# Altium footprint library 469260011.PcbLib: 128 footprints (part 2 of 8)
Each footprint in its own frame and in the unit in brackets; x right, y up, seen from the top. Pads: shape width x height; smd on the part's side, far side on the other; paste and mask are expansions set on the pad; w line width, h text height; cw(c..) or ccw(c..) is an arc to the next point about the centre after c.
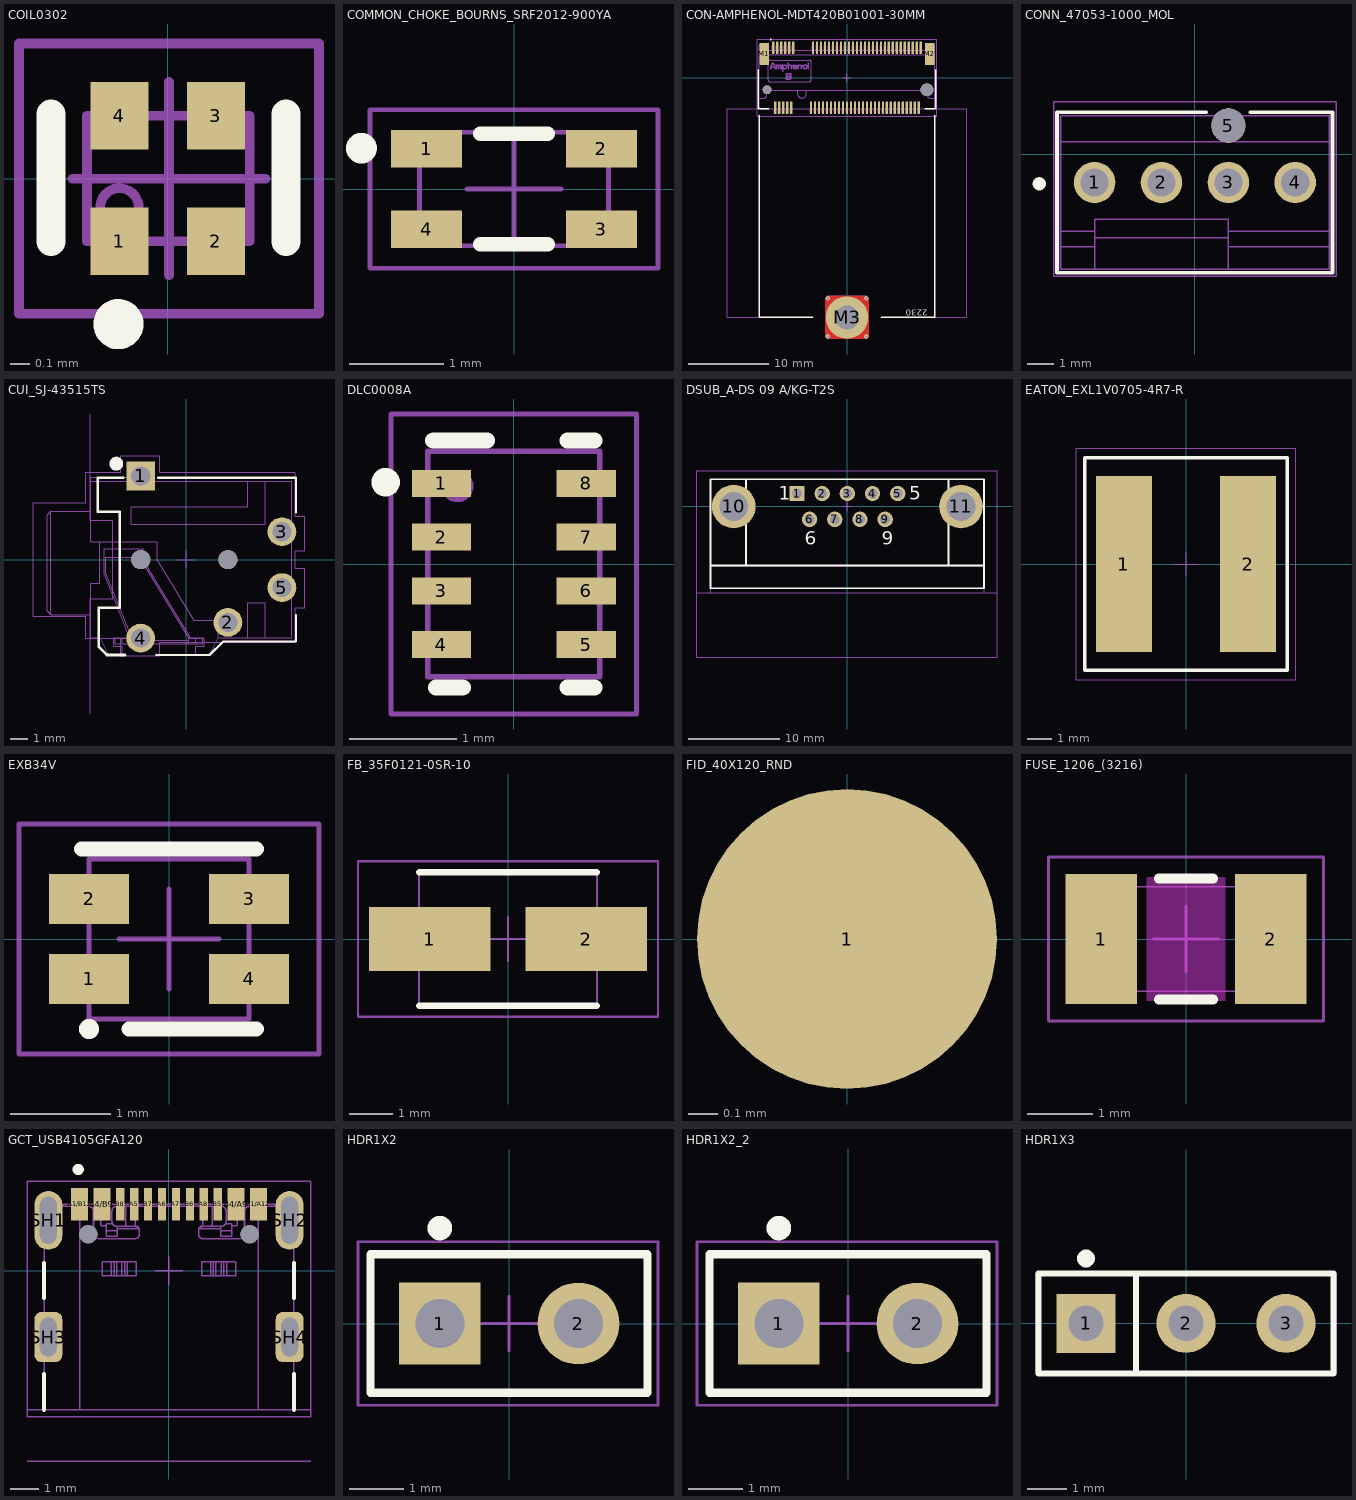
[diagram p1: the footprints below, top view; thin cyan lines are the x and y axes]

## COIL0302 [mm] "0302 (0806 Metric), 4 Lead"
height 0.5
pads (4):
  rect 0.3x0.35 smd: 1(-0.25,-0.325) 2(0.25,-0.325) 3(0.25,0.325) 4(-0.25,0.325)
Top Overlay:
  circle w0.152: c-0.255,-0.754 r0.054
  lines w0.15: -0.606,-0.325 -0.606,0.335 ; 0.614,-0.325 0.614,0.335
Top Assembly:
  circle w0.05: c-0.25,-0.15 r0.1
  lines w0.05: -0.35,-0.325 -0.35,-0.4 -0.15,-0.4 -0.15,-0.325 ; -0.35,0.325 -0.35,0.4 -0.15,0.4 -0.15,0.325 ; 0.157,-0.325 0.157,-0.4 0.357,-0.4 0.357,-0.325 ; 0.157,0.325 0.157,0.4 0.357,0.4 0.357,0.325 ; -0.418,-0.325 0.425,-0.325 0.425,0.325 -0.418,0.325 -0.418,-0.325
  text ".Designator" at -2.252,-0.226 h1
Top Courtyard:
  lines w0.05: -0.493,0 0.507,0 ; 0.007,-0.5 0.007,0.5 ; -0.77,-0.7 0.784,-0.7 0.784,0.7 -0.77,0.7 -0.77,-0.7
3D body "EXC-14CH120U.step": height 0.5, standoff 0, extent -0.425,-0.325 0.425,0.325

## COMMON_CHOKE_BOURNS_SRF2012-900YA [mm] "2.0x1.2x1.2mm"
height 2.4
pads (4):
  rect 0.75x0.4 smd: 1(-0.925,0.425) 2(0.925,0.425) 3(0.925,-0.425) 4(-0.925,-0.425)
Top Overlay:
  circle w0.254: c-1.615,0.432 r0.036
  lines w0.152: -0.356,-0.584 0.356,-0.584 ; -0.356,0.584 0.356,0.584
Top Assembly:
  lines w0.05: -1,-0.6 -1,0.6 1,0.6 1,-0.6 -1,-0.6
  text ".Designator" at -2.252,-0.226 h1
Top Courtyard:
  lines w0.05: -0.5,0 0.5,0 ; 0,-0.5 0,0.5 ; -1.524,-0.838 -1.524,0.838 1.524,0.838 1.524,-0.838 -1.524,-0.838 ; 0,0 0,0
3D body "User Library-SRF2012A.step": height 1.2, standoff 0.01, extent -1,-0.6 1,0.6

## CON-AMPHENOL-MDT420B01001-30MM [mm] "Tortadex footprint for PCIe M.2 Connectors, Storage and Server Connector, P=0.5mm, H=4.2mm, Key B, 30µin Au Plating"
height 4.2
pads (72):
  rrect10% 0.3x1.55 smd: 1(-9.25,3.775) 2(-9,-3.775) 3(-8.75,3.775) 4(-8.5,-3.775) 5(-8.25,3.775) 6(-8,-3.775) 7(-7.75,3.775) 8(-7.5,-3.775) 9(-7.25,3.775) 10(-7,-3.775) 11(-6.75,3.775) 20(-4.5,-3.775) 21(-4.25,3.775) 22(-4,-3.775) 23(-3.75,3.775) 24(-3.5,-3.775) 25(-3.25,3.775) 26(-3,-3.775) 27(-2.75,3.775) 28(-2.5,-3.775) 29(-2.25,3.775) 30(-2,-3.775) 31(-1.75,3.775) 32(-1.5,-3.775) 33(-1.25,3.775) 34(-1,-3.775) 35(-0.75,3.775) 36(-0.5,-3.775) 37(-0.25,3.775) 38(0,-3.775) 39(0.25,3.775) 40(0.5,-3.775) 41(0.75,3.775) 42(1,-3.775) 43(1.25,3.775) 44(1.5,-3.775) 45(1.75,3.775) 46(2,-3.775) 47(2.25,3.775) 48(2.5,-3.775) 49(2.75,3.775) 50(3,-3.775) 51(3.25,3.775) 52(3.5,-3.775) 53(3.75,3.775) 54(4,-3.775) 55(4.25,3.775) 56(4.5,-3.775) 57(4.75,3.775) 58(5,-3.775) 59(5.25,3.775) 60(5.5,-3.775) 61(5.75,3.775) 62(6,-3.775) 63(6.25,3.775) 64(6.5,-3.775) 65(6.75,3.775) 66(7,-3.775) 67(7.25,3.775) 68(7.5,-3.775) 69(7.75,3.775) 70(8,-3.775) 71(8.25,3.775) 72(8.5,-3.775) 73(8.75,3.775) 74(9,-3.775) 75(9.25,3.775)
  rrect10% 1.2x2.75 smd: M1(-10.35,3) M2(10.35,3)
  round 5.3 / inner round 0 / far side round 0 hole 3 unplated: M3(0,-30)
  round 1.1 hole 1.1 unplated: ""(-10,-1.5)
  round 1.6 hole 1.6 unplated: ""(10,-1.5)
via 2.4,-32.4 diameter 0.6 hole 0.3
via -2.4,-32.4 diameter 0.6 hole 0.3
via 2.4,-27.6 diameter 0.6 hole 0.3
via -2.4,-27.6 diameter 0.6 hole 0.3
Top Layer:
  region: -2.4,-27.3 -2.7,-27.6 -2.7,-32.4 -2.4,-32.7 0,-32.7 0,-31.9 -0.9,-31.9 -1.9,-30.9 -1.9,-29.1 -0.9,-28.1 0.9,-28.1 1.9,-29.1 1.9,-30.9 0.9,-31.9 0,-31.9 0,-32.7 2.4,-32.7 2.7,-32.4 2.7,-27.6 2.4,-27.3
Bottom Layer:
  region: -2.4,-27.3 -2.7,-27.6 -2.7,-32.4 -2.4,-32.7 0,-32.7 0,-31.9 -0.9,-31.9 -1.9,-30.9 -1.9,-29.1 -0.9,-28.1 0.9,-28.1 1.9,-29.1 1.9,-30.9 0.9,-31.9 0,-31.9 0,-32.7 2.4,-32.7 2.7,-32.4 2.7,-27.6 2.4,-27.3
Top Overlay:
  circle w0.15: c-9.55,4.8 r0.05
  lines w0.2: -11.1,1 -11.1,-3.9 -9.8,-3.9 ; -11,-4.7 -11,-30 -4.3,-30 ; 4.3,-30 11,-30 11,-4.7 ; 9.8,-3.9 11.1,-3.9 11.1,1
  text "2230" at 10.1,-28.815 h1.3
Top Paste:
  region: -2.542,-29.7 -2.517,-29.487 -2.397,-29.076 -2.21,-28.69 -1.962,-28.341 -1.659,-28.038 -1.31,-27.79 -0.924,-27.603 -0.513,-27.483 -0.3,-27.458 -0.3,-28.479 -0.411,-28.506 -0.627,-28.582 -0.828,-28.69 -1.012,-28.826 -1.174,-28.988 -1.31,-29.172 -1.418,-29.373 -1.494,-29.589 -1.521,-29.7
  region: 1.521,-29.7 1.494,-29.589 1.418,-29.373 1.31,-29.172 1.174,-28.988 1.012,-28.826 0.828,-28.69 0.627,-28.582 0.411,-28.506 0.3,-28.479 0.3,-27.458 0.513,-27.483 0.924,-27.603 1.31,-27.79 1.659,-28.038 1.962,-28.341 2.21,-28.69 2.397,-29.076 2.517,-29.487 2.542,-29.7
  region: 0.3,-32.542 0.3,-31.521 0.411,-31.494 0.627,-31.418 0.828,-31.31 1.012,-31.174 1.174,-31.012 1.31,-30.828 1.418,-30.627 1.494,-30.411 1.521,-30.3 2.542,-30.3 2.517,-30.513 2.397,-30.924 2.21,-31.31 1.962,-31.659 1.659,-31.962 1.31,-32.21 0.924,-32.397 0.513,-32.517
  region: -0.3,-31.521 -0.411,-31.494 -0.627,-31.418 -0.828,-31.31 -1.012,-31.174 -1.174,-31.012 -1.31,-30.828 -1.418,-30.627 -1.494,-30.411 -1.521,-30.3 -2.542,-30.3 -2.517,-30.513 -2.397,-30.924 -2.21,-31.31 -1.962,-31.659 -1.659,-31.962 -1.31,-32.21 -0.924,-32.397 -0.513,-32.517 -0.3,-32.542
Bottom Solder:
  region: -1.6,-30 -1.6,-29.842 -1.539,-29.533 -1.418,-29.242 -1.243,-28.98 -1.02,-28.757 -0.758,-28.582 -0.467,-28.462 -0.158,-28.4 0,-28.4 0.158,-28.4 0.467,-28.462 0.758,-28.582 1.02,-28.757 1.243,-28.98 1.418,-29.242 1.539,-29.533 1.6,-29.842 1.6,-30 1.6,-30.158 1.539,-30.467 1.418,-30.758 1.243,-31.02 1.02,-31.243 0.758,-31.418 0.467,-31.539 0.158,-31.6 0,-31.6 -0.158,-31.6 -0.467,-31.539 -0.758,-31.418 -1.02,-31.243 -1.243,-31.02 -1.418,-30.758 -1.539,-30.467 -1.6,-30.158
Top Assembly:
  drawing of 2595 lines, arcs and shapes, not listed
  text ".Designator" at -2.252,-0.226 h1
Top Courtyard:
  lines w0.05: -0.5,0 0.5,0 ; 0,-0.5 0,0.5 ; -11.25,-4.8 -11.25,4.8 11.25,4.8 11.25,-4.8 -11.25,-4.8
3D body "User Library-m2_type3052_b_4ant-1.STEP": height 4.69, standoff 1.19, extent -15,-52 15,0
3D body "c-2199230-1-b3-3d.stp": height 4.1, standoff -0.6, extent -10.939,-4.378 10.961,4.322

## CONN_47053-1000_MOL [mil]
height 295.28
pads (5):
  round 62 / inner round 60 / far side round 62 hole 42 paste+0 mask+0: 1(-150,-42.52) 2(-50,-42.52) 3(50,-42.52) 4(150,-42.52)
  round 51 / inner round 60 / far side round 51 hole 51 unplated paste+0 mask-25.5: 5(50,42.52)
Top Overlay:
  circle w9.84: c-232.68,-44.49 r4.92
  lines w5.91: 16.96,62.48 -206,62.48 -206,-177.52 206,-177.52 206,62.48 83.04,62.48
Top 3D Body:
  lines w1: -201,-172.52 -201,57.48 201,57.48 201,-172.52 -201,-172.52
Top Assembly:
  drawing of 316 lines, arcs and shapes, not listed
Top Courtyard:
  lines w1.97: -211,-182.52 211,-182.52 211,78.02 -211,78.02 -211,-182.52
3D body "470531000.stp": height 413.39, standoff -118.11, extent -200.79,-172.44 200.79,57.48

## CUI_SJ-43515TS [mm] "3.5 mm, Stereo, Right Angle, Through Hole, 4 Conductors, 1 Internal Tip Switches, Audio Jack Connector"
height 5
pads (7):
  rect 1.65x1.65 / inner round 1.65 / far side rect 1.65x1.65 hole 1.1: 1(-2.6,4.8)
  round 1.65 hole 1.1: 2(2.4,-3.6) 3(5.5,1.6) 4(-2.6,-4.5) 5(5.5,-1.6)
  round 1.1 hole 1.1 unplated: ""(-2.6,0) ""(2.4,0)
Top Overlay:
  circle w0.4: c-4,5.5 r0.2
  lines w0.127: -1.7,-5.466 1.35,-5.466 2.116,-4.7 6.3,-4.7 6.3,-3.166 ; -1.6,4.7 6.3,4.7 6.3,2.7
  lines w0.15: -3.6,4.7 -5.05,4.7 -5.05,3.45 -5.05,2.75 -3.8,2.75 -3.8,-2.75 -5,-2.75 -5,-3.5 -5,-5 -4.534,-5.466 -3.5,-5.466
Mechanical 1:
  lines w0.05: -5.5,-8.85 -5.5,-2.25 -4.2,-2.25 -4.2,2.25 -5.5,2.25 -5.5,8.35
  text "PCB EDGE" at -5,-7.5 h0.61
Top Assembly:
  lines w0.05: -5.45,-3.151 -7.75,-3.151 ; -5.45,2.763 -7.75,2.763 ; -5.45,4.504 6.05,4.504 6.05,-4.466 1.85,-4.466 ; -4.95,1.033 -4.95,-1.365 -5.45,-1.365 -5.45,-4.466 -4.95,-4.466 -4.45,-5.466 -3.65,-5.466 -3.65,-4.966 -4.15,-4.966 -4.15,-4.466 -3.142,-4.466 ; -3.65,-4.816 -3.65,-4.516 ; -3.25,-4.466 -4.7,-0.866 -4.7,0.634 -2.45,0.634 -2.45,-0.066 0.25,-4.466 ; -3.122,-4.816 -3.122,-4.516 ; -3.122,-4.616 0.163,-4.616 ; -2.15,4.504 -2.15,4.734 -5.45,4.734 -5.45,1.033 -1.65,1.033 -1.65,-0.031 0.458,-3.466 1.85,-3.466 1.85,-4.466 ; 0.133,-4.466 1.05,-4.466 1.05,-4.966 0.55,-4.966 0.55,-5.466 1.35,-5.466 1.85,-4.466 ; 0.163,-4.816 0.163,-4.516 ; 0.55,-4.816 0.55,-4.516 ; 3.55,-4.466 3.55,-2.466 4.55,-2.466 4.55,-4.466 ; 3.55,4.504 3.55,3.034 -3.15,3.034 -3.15,2.034 4.55,2.034 4.55,4.504 ; -7.75,-3.151 -7.75,2.763 ; -7.75,-3.151 -7.759,-3.142 -7.768,-3.133 -7.777,-3.124 -7.786,-3.115 -7.795,-3.106 -7.804,-3.097 -7.813,-3.088 -7.822,-3.078 -7.832,-3.069 -7.841,-3.059 -7.851,-3.049 -7.861,-3.039 -7.871,-3.03 -7.881,-3.02 -7.891,-3.009 -7.901,-2.999 -7.911,-2.989 -7.921,-2.979 -7.932,-2.968 -7.942,-2.957 -7.95,-2.95 -7.95,2.558 -7.939,2.569 -7.929,2.579 -7.918,2.59 -7.908,2.601 -7.898,2.611 -7.888,2.621 -7.878,2.632 -7.868,2.642 -7.858,2.652 -7.849,2.662 -7.839,2.671 -7.83,2.681 -7.82,2.691 -7.811,2.7 -7.802,2.71 -7.793,2.719 -7.784,2.728 -7.775,2.737 -7.766,2.746 -7.758,2.755 -7.75,2.763 ; -3.122,-4.516 -4.6,-0.846 -4.6,0.134 -2.55,0.134 -2.55,-0.094 0.163,-4.516 ; -3.122,-4.516 -4.05,-4.516 -4.05,-4.816 0.95,-4.816 0.95,-4.516 0.163,-4.516
  text ".Designator" at -1.702,-0.207 h1
Top Courtyard:
  lines w0.05: -0.5,0 0.5,0 ; 0,-0.5 0,0.5 ; -8.75,-3.25 -8.75,3.25 -5.75,3.25 -5.75,5 -3.75,5 -3.75,5.95 -1.5,5.95 -1.5,5 6.25,5 6.25,2.5 6.8,2.5 6.8,0.5 6.25,0.5 6.25,-0.5 6.8,-0.5 6.8,-2.75 6.25,-2.75 6.25,-4.75 -1.5,-4.75 -1.5,-5.5 -3.75,-5.5 -3.75,-4.5 -5.75,-4.5 -5.75,-3.25 -8.75,-3.25
3D body "CUI_DEVICES_SJ-43515TS.step": height 5.29, standoff -1.95, extent -7.95,-5.481 6.05,4.719

## DLC0008A [mm]
pads (8):
  rect 0.55x0.25 smd paste+0 mask+0.051: 1(-0.675,0.75) 2(-0.675,0.25) 3(-0.675,-0.25) 4(-0.675,-0.75) 5(0.675,-0.75) 6(0.675,-0.25) 7(0.675,0.25) 8(0.675,0.75)
Top Overlay:
  circle w0.152: c-1.194,0.762 r0.057
  lines w0.15: -0.75,1.15 -0.25,1.15 ; -0.725,-1.15 -0.475,-1.15 ; 0.5,-1.15 0.75,-1.15 ; 0.5,1.15 0.75,1.15
Top Assembly:
  circle w0.05: c-0.525,0.725 r0.125
  lines w0.05: -0.8,-1.05 -0.8,1.05 0.8,1.05 0.8,-1.05 -0.8,-1.05
Top Courtyard:
  lines w0.05: -1.143,-1.397 -1.143,1.397 1.143,1.397 1.143,-1.397 -1.143,-1.397
3D body "DLC0008A.stp": height 0.92, standoff -0.08, extent -0.762,-0.991 0.738,1.009

## DSUB_A-DS 09 A/KG-T2S [mm] "Connector; D Subminiature; 9 Position; Right Angle; Pitch 1.385 mm"
height 12.55
pads (11):
  rect 1.69x1.69 hole 1.09: 1(-5.54,1.42)
  round 1.69 hole 1.09: 2(-2.77,1.42) 3(0,1.42) 4(2.77,1.42) 5(5.54,1.42) 6(-4.155,-1.42) 7(-1.385,-1.42) 8(1.385,-1.42) 9(4.155,-1.42)
  round 4.8 hole 3.18: 10(-12.495,0) 11(12.495,0)
Top Overlay:
  lines w0.2: -15.04,-6.5 15.04,-6.5 ; -11.14,-6.5 -11.14,3 ; 11.14,-6.5 11.14,3 ; -15.04,-9 15.04,-9 15.04,3 -15.04,3 -15.04,-9
  text "5" at 6.833,0.734 h1.5
  text "1" at -7.569,0.734 h1.5
  text "9" at 3.759,-4.193 h1.5
  text "6" at -4.699,-4.193 h1.5
Mechanical 1:
  lines w0.05: -16.54,-9.5 16.46,-9.5
  text "PCB Edge" at -3.832,-8.913 h1
Top Assembly:
  lines w0.05: -15.04,-6.5 15.04,-6.5 ; -11.14,-6.5 -11.14,3 ; 11.14,-6.5 11.14,3 ; -15.04,-9.5 15.04,-9.5 15.04,3 -15.04,3 -15.04,-9.5
  text ".Designator" at -2.252,-0.226 h1
Top Courtyard:
  lines w0.05: -0.5,0 0.5,0 ; 0,-0.5 0,0.5 ; -16.54,-16.58 16.46,-16.58 16.46,3.92 -16.54,3.92 -16.54,-16.58
3D body "connector_a-ds_09_a_kg-t2.stp": height 12.57, standoff -4.3, extent -15.405,-15.656 15.405,2.944

## EATON_EXL1V0705-4R7-R [mm] "8.40mm x 8.00mm x 5mm"
height 5
pads (2):
  rect 2.3x7.2 smd: 1(-2.55,0) 2(2.55,0)
Top Overlay:
  lines w0.15: -4.153,-4.35 4.153,-4.35 4.153,4.356 -4.153,4.356 -4.153,-4.35
Top Assembly:
  lines w0.05: -4.153,-4.35 4.153,-4.35 4.153,4.356 -4.153,4.356 -4.153,-4.35
  text ".Designator" at -2.252,-0.226 h1
Top Courtyard:
  lines w0.05: -0.5,0 0.5,0 ; 0,-0.5 0,0.5 ; -4.5,-4.75 -4.5,4.75 4.5,4.75 4.5,-4.75 -4.5,-4.75
3D body "IND_EXL1V0705-3R3-R_EAT.step": height 5.01, standoff 0, extent -4.153,-4.356 4.153,4.356

## EXB34V [mm] "Chip Resistor Array, (0603x2); SM; 4 Leads; Body 1.80 x 1.75 mm (LxW max)"
height 0.6
pads (4):
  rect 0.8x0.5 smd: 1(-0.8,-0.4) 2(-0.8,0.4) 3(0.8,0.4) 4(0.8,-0.4)
Top Overlay:
  circle w0.1: c-0.8,-0.9 r0.05
  lines w0.15: -0.875,0.9 0.875,0.9 ; -0.4,-0.9 0.875,-0.9
Top Assembly:
  lines w0.05: -0.8,-0.55 ccw(c-0.8,-0.4) -0.8,-0.25 ; -0.8,0.25 ccw(c-0.8,0.4) -0.8,0.55 ; 0.8,-0.55 cw(c0.8,-0.4) 0.8,-0.25 ; 0.8,0.25 cw(c0.8,0.4) 0.8,0.55 ; -0.8,-0.8 -0.8,0.8 0.8,0.8 0.8,-0.8 -0.8,-0.8
  text ".Designator" at -2.252,0.226 h1
Top Courtyard:
  lines w0.05: -0.5,0 0.5,0 ; 0,-0.5 0,0.5 ; -1.5,-1.15 -1.5,1.15 1.5,1.15 1.5,-1.15 -1.5,-1.15
3D body "User Library-EXBV4V.step": height 0.53, standoff -0.03, extent -0.8,-0.8 0.8,0.8

## FB_35F0121-0SR-10 [mm] "FERRITE BEAD 1612 (4131 Metric)"
height 2.54
pads (2):
  rect 2.77x1.47 smd: 1(-1.79,0) 2(1.79,0)
Top Overlay:
  lines w0.15: -2.03,-1.525 2.03,-1.525 ; -2.03,1.525 2.03,1.525
Top Assembly:
  lines w0.05: -2.03,-1.525 2.03,-1.525 2.03,1.525 -2.03,1.525 -2.03,-1.525
  text ".Designator" at -2.433,-0.226 h1
Top Courtyard:
  lines w0.05: -0.5,0 0.5,0 ; 0,-0.5 0,0.5 ; -3.425,-1.775 -3.425,1.775 3.425,1.775 3.425,-1.775 -3.425,-1.775
3D body "step_temp.STEP": height 3.05, standoff 0, extent -2.54,-1.525 2.54,1.525

## FID_40X120_RND [mil]
height 551.18
pads (1):
  round 40 smd paste-40 mask+40: 1(0,0)

## FUSE_1206_(3216) [mm] "FUSE SMD 1206 (3216 Metric)"
pads (2):
  rect 1.1x2 smd paste+0 mask+0: 1(-1.302,0) 2(1.302,0)
Top Layer keep-out:
  region: -0.6,-0.95 -0.6,0.95 0.6,0.95 0.6,-0.95
Top Overlay:
  lines w0.15: -0.417,-0.927 0.417,-0.927 ; -0.417,0.927 0.417,0.927
Top Assembly:
  lines w0.025: -1.6,-0.8 -1.6,0.8 1.6,0.8 1.6,-0.8 -1.6,-0.8
  text ".Designator" at -2.433,-0.226 h1
Top Courtyard:
  lines w0.05: -0.5,0 0.5,0 ; 0,-0.5 0,0.5 ; -2.108,-1.257 -2.108,1.257 -1.854,1.257 1.854,1.257 2.108,1.257 2.108,-1.257 1.854,-1.257 -1.854,-1.257 -2.108,-1.257
3D body "User Library-0466_500NRHF.step": height 0.54, standoff -0.04, extent -1.587,-0.762 1.587,0.762

## GCT_USB4105GFA120 [mm] "USB-C (USB TYPE-C) USB 2.0 Receptacle Connector 24 (16+8 Dummy) Position Surface Mount, Right Angle; Through Hole"
height 3.31
pads (18):
  rect 0.6x1.15 smd: A1/B12(-3.2,2.378) A4/B9(-2.4,2.378) B1/A12(3.2,2.378) B4/A9(2.4,2.378)
  rect 0.3x1.15 smd: A5(-1.25,2.378) A6(-0.25,2.378) A7(0.25,2.378) A8(1.25,2.378) B5(1.75,2.378) B6(0.75,2.378) B7(-0.75,2.378) B8(-1.75,2.378)
  oval 1x2.1 hole 0.6 slot 1.7 at 90 deg: SH1(-4.32,1.803) SH2(4.32,1.803)
  rrect50% 1x1.8 hole 0.6 slot 1.4 at 90 deg: SH3(-4.32,-2.377) SH4(4.32,-2.377)
  round 0.65 hole 0.65 unplated: ""(-2.89,1.303) ""(2.89,1.303)
Top Overlay:
  circle w0.2: c-3.25,3.623 r0.1
  lines w0.15: -4.47,-4.977 -4.47,-3.697 ; -4.47,-0.977 -4.47,0.273 ; 4.47,-4.977 4.47,-3.697 ; 4.47,-0.977 4.47,0.273
Mechanical 1:
  lines w0.05: -5.07,-6.828 5.07,-6.828 ; -5.07,-4.979 -4.47,-4.979 ; 5.07,-4.977 4.47,-4.977 ; 4.47,-4.977 -4.47,-4.977 -4.47,2.373 4.47,2.373 4.47,-4.977
  text "PCB EDGE" at -1.126,-4.871 h0.5
  text "PLUG EDGE" at -1.275,-6.722 h0.5
Top Assembly:
  drawing of 639 lines, arcs and shapes, not listed
  text ".Designator" at -2.252,-0.226 h1
Top Courtyard:
  lines w0.05: -0.5,0 0.5,0 ; 0,-0.5 0,0.5 ; -5.07,-5.227 -5.07,3.203 5.07,3.203 5.07,-5.227 -5.07,-5.227
3D body "usb4105-xx-a-060.stp": height 3.26, standoff -0.63, extent -4.47,-4.978 4.47,2.722

## HDR1X2 [mm] "Connector; Header; 2 Position"
pads (2):
  rect 1.5x1.5 hole 0.9: 1(-1.27,0)
  round 1.5 hole 0.9: 2(1.27,0)
Top Overlay:
  circle w0.25: c-1.27,1.75 r0.1
  lines w0.15: -2.54,-1.27 2.54,-1.27 2.54,1.27 -2.54,1.27 -2.54,-1.27
Top Assembly:
  lines w0.05: -2.54,-1.27 -2.54,1.27 2.54,1.27 2.54,-1.27 -2.54,-1.27
  text ".Designator" at -0.719,-0.316 h1
Top Courtyard:
  lines w0.05: -0.5,0 0.5,0 ; 0,-0.5 0,0.5 ; -2.77,-1.5 -2.77,1.5 2.73,1.5 2.73,-1.5 -2.77,-1.5

## HDR1X2_2 [mm]
pads (2):
  rect 1.5x1.5 hole 0.9: 1(-1.27,0)
  round 1.5 hole 0.9: 2(1.27,0)
Top Overlay:
  circle w0.25: c-1.27,1.75 r0.1
  lines w0.15: -2.54,-1.27 2.54,-1.27 2.54,1.27 -2.54,1.27 -2.54,-1.27
Top Assembly:
  lines w0.05: -2.54,-1.27 -2.54,1.27 2.54,1.27 2.54,-1.27 -2.54,-1.27
  text ".Designator" at -2.433,-0.226 h1
Top Courtyard:
  lines w0.05: -0.5,0 0.5,0 ; 0,-0.5 0,0.5 ; -2.77,-1.5 -2.77,1.5 2.73,1.5 2.73,-1.5 -2.77,-1.5

## HDR1X3 [mm] "Connector; Header; 3 Position"
pads (3):
  rect 1.5x1.5 hole 0.9: 1(-2.54,0)
  round 1.5 hole 0.9: 2(0,0) 3(2.54,0)
Top Overlay:
  circle w0.254: c-2.54,1.65 r0.1
  lines w0.15: -1.27,-1.27 -1.27,1.27 ; -3.75,-1.27 3.75,-1.27 3.75,1.27 -3.75,1.27 -3.75,-1.27
Top Assembly:
  lines w0.05: -1.27,-1.27 -1.27,1.27 ; -3.81,-1.27 -3.81,1.27 3.81,1.27 3.81,-1.27 -3.81,-1.27 ; -3,-0.45 -2.1,-0.45 -2.1,0.45 -3,0.45 -3,-0.45
  text ".Designator" at -2.252,-0.226 h1
Top Courtyard:
  lines w0.05: -0.5,0 0.5,0 ; 0,-0.5 0,0.5 ; -3.81,-1.27 3.81,-1.27 3.81,1.27 -3.81,1.27 -3.81,-1.27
